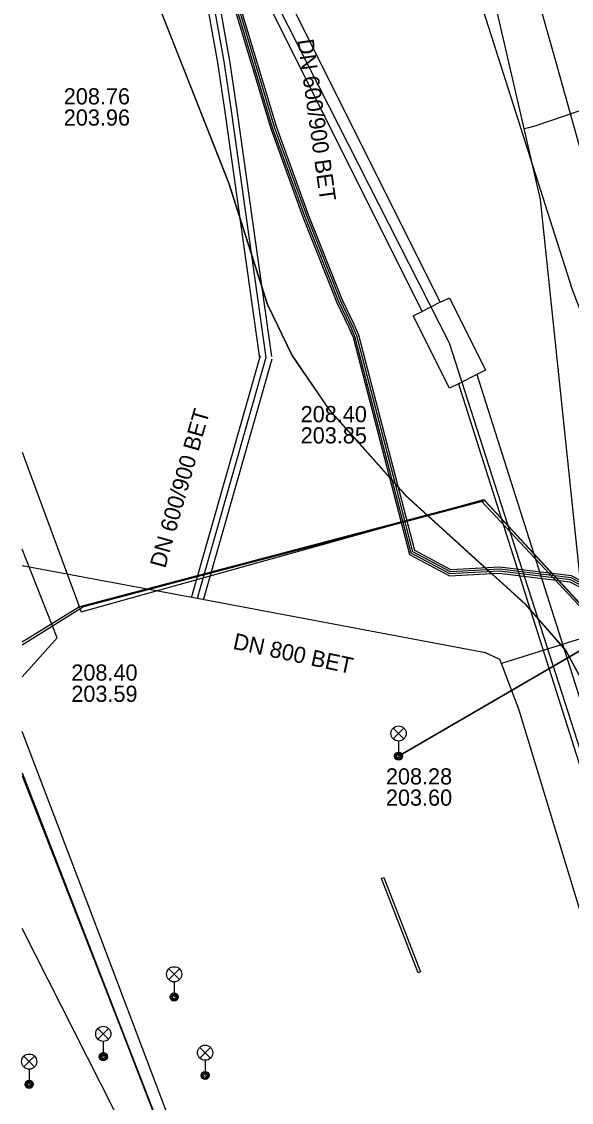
# Model space of a CAD drawing. Extents: x -595540 to -593988, y -1160850 to -1159202.
# Drawn here: x -595539.6 to -595512.4, y -1160240.3 to -1160186.8 of the extents above; entities that cross this region are included whole.
import ezdxf

# ---------------------------------------------------------------- set-up
doc = ezdxf.new("R2010")
doc.units = 0
for name, color, linetype in [('BKOM-ODVODNENI_objekt', 7, 'Continuous'), ('BKOM_kabel koordinační_optický', 7, 'Continuous'), ('BVK-JEDNOTNA_popisy', 7, 'Continuous'), ('BVK-JEDNOTNA_trasa sítě', 7, 'Continuous'), ('BVK-JEDNOTNA_trasa sítě obvodem', 7, 'Continuous'), ('BVK-VODOVOD_trasa sítě', 7, 'Continuous'), ('CETIN_kabel podzemní', 7, 'Continuous'), ('CETIN_kabelovod', 7, 'Continuous'), ('DPMB_trolejové vedení-nosné lano', 7, 'Continuous'), ('EON-SDEL_kabel', 7, 'Continuous'), ('EON-VN_kabel', 7, 'Continuous'), ('INNOGY-NTL_trasa sítě', 7, 'Continuous'), ('QUANTCOM_kabel', 7, 'Continuous'), ('TSB_kabel VO', 7, 'Continuous'), ('TSB_lampy VO', 7, 'Continuous')]:
    doc.layers.add(name, color=color, linetype=linetype)

msp = doc.modelspace()

# ---------------------------------------------------------------- linework, layer by layer
at = {"layer": 'BKOM-ODVODNENI_objekt'}
msp.add_lwpolyline([(-595520.01, -1160233.89), (-595521.83, -1160229.22), (-595521.71, -1160229.17), (-595519.89, -1160233.84)], close=True, dxfattribs=at)
at = {"layer": 'BKOM_kabel koordinační_optický'}
for points in [[(-595539.58, -1160219.244), (-595537.85, -1160217.31), (-595539.58, -1160212.925)], [(-595513.85, -1160288.56), (-595514.78, -1160289.19), (-595514.85, -1160286.98), (-595516.46, -1160285.31), (-595519.18, -1160278.38), (-595519.73, -1160274.57), (-595521.55, -1160271.88), (-595526.04, -1160260.69), (-595528.26, -1160254.82), (-595528.69, -1160251.43), (-595531.52, -1160243.2), (-595536.29, -1160230.6), (-595539.58, -1160221.945)]]:
    msp.add_lwpolyline(points, dxfattribs=at)
at = {"layer": 'BVK-JEDNOTNA_popisy'}
for p, q in [((-595537.522, -1160191.06), (-595537.522, -1160191.06)), ((-595525.817, -1160206.778), (-595525.817, -1160206.778)), ((-595537.15, -1160219.559), (-595537.15, -1160219.559)), ((-595521.606, -1160224.695), (-595521.606, -1160224.695))]:
    msp.add_line(p, q, dxfattribs=at)
at = {"layer": 'BVK-JEDNOTNA_trasa sítě'}
for p, q in [((-595529.245, -1160191.262), (-595527.537, -1160203.446)), ((-595527.537, -1160203.446), (-595530.93, -1160215.37)), ((-595530.93, -1160215.37), (-595539.58, -1160213.76))]:
    msp.add_line(p, q, dxfattribs=at)
for points in [[(-595539.58, -1160158.382), (-595538.785, -1160160.074), (-595537.726, -1160162.476), (-595536.956, -1160164.225), (-595536.25, -1160165.901), (-595535.634, -1160167.414), (-595534.973, -1160169.118), (-595534.34, -1160170.804), (-595533.479, -1160173.278), (-595532.719, -1160175.58), (-595531.904, -1160178.371), (-595530.872, -1160182.503), (-595530.202, -1160185.494), (-595529.609, -1160188.822), (-595529.245, -1160191.262)], [(-595502.779, -1160214.506), (-595504.78, -1160215.129), (-595506.59, -1160215.692), (-595512.412, -1160217.505), (-595515.893, -1160218.588)], [(-595515.893, -1160218.588), (-595515.969, -1160218.384), (-595516.679, -1160218.051), (-595530.93, -1160215.37)], [(-595501.932, -1160264.015), (-595515.017, -1160220.901), (-595515.893, -1160218.588)]]:
    msp.add_lwpolyline(points, dxfattribs=at)
at = {"layer": 'BVK-JEDNOTNA_trasa sítě obvodem'}
for p, q in [((-595527.834, -1160203.488), (-595529.542, -1160191.304)), ((-595527.24, -1160203.404), (-595528.948, -1160191.22)), ((-595527.826, -1160203.364), (-595531.219, -1160215.288)), ((-595527.248, -1160203.528), (-595530.641, -1160215.452))]:
    msp.add_line(p, q, dxfattribs=at)
for points in [[(-595528.948, -1160191.218), (-595529.313, -1160188.774), (-595529.907, -1160185.435), (-595530.58, -1160182.434), (-595531.614, -1160178.292), (-595532.432, -1160175.491), (-595533.195, -1160173.181), (-595534.057, -1160170.702), (-595534.693, -1160169.011), (-595535.356, -1160167.304), (-595535.973, -1160165.786), (-595536.681, -1160164.106), (-595537.451, -1160162.354), (-595538.512, -1160159.95), (-595539.58, -1160157.676)], [(-595529.542, -1160191.306), (-595529.905, -1160188.871), (-595530.496, -1160185.553), (-595531.164, -1160182.572), (-595532.193, -1160178.449), (-595533.005, -1160175.669), (-595533.763, -1160173.374), (-595534.622, -1160170.906), (-595535.254, -1160169.225), (-595535.913, -1160167.525), (-595536.527, -1160166.016), (-595537.232, -1160164.343), (-595538, -1160162.596), (-595539.058, -1160160.198), (-595539.58, -1160159.088)]]:
    msp.add_lwpolyline(points, dxfattribs=at)
at = {"layer": 'BVK-VODOVOD_trasa sítě'}
for points in [[(-595511.7, -1160217.366), (-595513.961, -1160195.642), (-595514.772, -1160192.124), (-595516.052, -1160186.573), (-595516.602, -1160184.188), (-595518.91, -1160174.175), (-595519.059, -1160173.529), (-595521.452, -1160170.03), (-595521.642, -1160169.757), (-595529.075, -1160158.883), (-595537.262, -1160146.913), (-595539.58, -1160143.525)], [(-595514.772, -1160192.124), (-595514.545, -1160192.072), (-595514.236, -1160192.001), (-595508.525, -1160190.053)]]:
    msp.add_lwpolyline(points, dxfattribs=at)
at = {"layer": 'CETIN_kabel podzemní'}
msp.add_lwpolyline([(-595502.07, -1160293.44), (-595490.46, -1160289.89), (-595518.47, -1160202.74), (-595539.4, -1160161.52), (-595539.58, -1160161.248)], dxfattribs=at)
at = {"layer": 'CETIN_kabelovod'}
for points in [[(-595537.6, -1160163.33), (-595518.92, -1160200.72)], [(-595538.44, -1160163.88), (-595519.81, -1160201.17)], [(-595518.92, -1160200.72), (-595519.81, -1160201.17)], [(-595518.92, -1160200.72), (-595518.47, -1160200.5), (-595516.68, -1160204.08), (-595517.12, -1160204.3)], [(-595518.02, -1160204.75), (-595518.46, -1160204.97), (-595520.26, -1160201.4), (-595519.81, -1160201.17)], [(-595517.12, -1160204.3), (-595518.02, -1160204.75)], [(-595517.12, -1160204.3), (-595490.74, -1160287.35)], [(-595518.02, -1160204.75), (-595491.7, -1160287.66)]]:
    msp.add_lwpolyline(points, dxfattribs=at)
at = {"layer": 'DPMB_trolejové vedení-nosné lano'}
msp.add_lwpolyline([(-595529.889, -1160250.835), (-595539.58, -1160231.693)], dxfattribs=at)
at = {"layer": 'EON-SDEL_kabel'}
for points in [[(-595539.58, -1160171.985), (-595537.716, -1160175.427), (-595534.786, -1160180.567), (-595532.666, -1160186.487), (-595529.366, -1160194.837), (-595527.456, -1160200.837), (-595526.236, -1160203.357), (-595524.406, -1160206.047), (-595521.43, -1160209.384), (-595521.139, -1160209.711), (-595520.616, -1160210.297), (-595516.6, -1160213.952), (-595516.392, -1160214.141), (-595514.716, -1160215.667), (-595512.716, -1160217.947), (-595510.466, -1160222.127), (-595508.176, -1160227.937), (-595507.99, -1160228.201)], [(-595529.119, -1160186.065), (-595527.3, -1160192.123), (-595525.687, -1160196.551), (-595524.023, -1160200.74), (-595523.452, -1160201.943), (-595523.229, -1160202.446), (-595521.43, -1160209.384), (-595520.442, -1160213.195), (-595518.465, -1160214.253), (-595516.392, -1160214.141), (-595516.007, -1160214.121), (-595512.52, -1160214.544), (-595507.042, -1160217.402), (-595505.473, -1160218.455), (-595504.631, -1160219.689), (-595504.625, -1160219.707), (-595503.142, -1160224.197), (-595501.133, -1160231.693), (-595499.333, -1160238.134), (-595497.192, -1160245.755)], [(-595497, -1160245.7), (-595499.14, -1160238.08), (-595500.94, -1160231.64), (-595502.95, -1160224.14), (-595504.45, -1160219.6), (-595504.491, -1160219.54), (-595505.33, -1160218.31), (-595506.94, -1160217.23), (-595512.46, -1160214.35), (-595516, -1160213.92), (-595516.6, -1160213.952), (-595518.42, -1160214.05), (-595520.27, -1160213.06), (-595521.139, -1160209.711), (-595523.04, -1160202.38), (-595523.271, -1160201.859), (-595523.84, -1160200.66), (-595525.5, -1160196.48), (-595527.11, -1160192.06), (-595528.93, -1160186)]]:
    msp.add_lwpolyline(points, dxfattribs=at)
at = {"layer": 'EON-VN_kabel'}
for points in [[(-595497.096, -1160245.727), (-595499.236, -1160238.107), (-595501.036, -1160231.666), (-595503.046, -1160224.169), (-595504.541, -1160219.645), (-595505.402, -1160218.382), (-595506.991, -1160217.316), (-595512.49, -1160214.447), (-595516.003, -1160214.02), (-595518.443, -1160214.151), (-595520.356, -1160213.127), (-595523.135, -1160202.413), (-595523.361, -1160201.902), (-595523.932, -1160200.7), (-595525.593, -1160196.516), (-595527.205, -1160192.092), (-595529.025, -1160186.032)], [(-595496.904, -1160245.673), (-595499.044, -1160238.053), (-595500.843, -1160231.614), (-595502.854, -1160224.111), (-595504.359, -1160219.555), (-595505.258, -1160218.238), (-595506.889, -1160217.144), (-595512.43, -1160214.253), (-595515.997, -1160213.82), (-595518.398, -1160213.949), (-595520.184, -1160212.993), (-595522.945, -1160202.347), (-595523.18, -1160201.817), (-595523.748, -1160200.62), (-595525.407, -1160196.444), (-595527.015, -1160192.028), (-595528.835, -1160185.968)]]:
    msp.add_lwpolyline(points, dxfattribs=at)
at = {"layer": 'INNOGY-NTL_trasa sítě'}
msp.add_lwpolyline([(-595506.82, -1160211.71), (-595507.03, -1160210.99), (-595508.06, -1160207.27), (-595509.9, -1160200.76), (-595511.13, -1160196.03), (-595512.1, -1160192.75), (-595513.19, -1160188.87), (-595514.44, -1160184.41), (-595514.56, -1160184.02), (-595514.76, -1160183.23), (-595515.33, -1160181.38), (-595516.49, -1160177.7), (-595519.3, -1160169.86), (-595519.39, -1160169.63), (-595519.63, -1160168.99), (-595519.78, -1160168.59), (-595519.92, -1160168.21), (-595519.58, -1160166.8), (-595525.76, -1160157.36)], dxfattribs=at)
at = {"layer": 'QUANTCOM_kabel'}
msp.add_lwpolyline([(-595507.99, -1160228.2), (-595508.17, -1160227.93), (-595510.46, -1160222.12), (-595512.71, -1160217.94), (-595514.71, -1160215.66), (-595520.61, -1160210.29), (-595524.4, -1160206.04), (-595526.23, -1160203.35), (-595527.45, -1160200.83), (-595529.36, -1160194.83), (-595532.66, -1160186.48), (-595534.78, -1160180.56), (-595537.71, -1160175.42), (-595539.58, -1160171.967)], dxfattribs=at)
at = {"layer": 'TSB_kabel VO'}
for points in [[(-595497.74, -1160230.67), (-595502.35, -1160228.99), (-595504.75, -1160218.47), (-595504.46, -1160214.78), (-595505.94, -1160214.71), (-595508.22, -1160206.5), (-595511.02, -1160203.66), (-595512.39, -1160200.1), (-595520.06, -1160176), (-595523.89, -1160167.79), (-595529.64, -1160159.03), (-595539.58, -1160144.314)], [(-595539.58, -1160208.135), (-595536.67, -1160216.03), (-595516.77, -1160210.48), (-595510.61, -1160217.142)], [(-595497.65, -1160230.7), (-595502.48, -1160228.88), (-595503.61, -1160224.76), (-595516.71, -1160210.54), (-595536.55, -1160215.78), (-595539.58, -1160217.688)], [(-595497.62, -1160230.7), (-595502.48, -1160229.07), (-595503.42, -1160224.95), (-595516.9, -1160210.54), (-595536.74, -1160215.78), (-595539.58, -1160217.533)], [(-595497.65, -1160230.7), (-595502.48, -1160229.07), (-595503.42, -1160224.95), (-595516.71, -1160210.54), (-595536.74, -1160215.78), (-595539.58, -1160217.533)], [(-595510.61, -1160217.142), (-595520.98, -1160223.17), (-595510.61, -1160217.142)], [(-595539.58, -1160223.991), (-595530.88, -1160246.43), (-595518.58, -1160278.48), (-595512.78, -1160294.77), (-595534.3, -1160302.07), (-595536.55, -1160296.26), (-595538.703, -1160293.66)], [(-595539.58, -1160224.012), (-595531.12, -1160245.92), (-595518.58, -1160278.3), (-595512.59, -1160294.95), (-595534.12, -1160302.07), (-595532.25, -1160308.24), (-595531.83, -1160309.236)], [(-595539.58, -1160224.14), (-595530.94, -1160246.29), (-595520.244, -1160274.255)]]:
    msp.add_lwpolyline(points, dxfattribs=at)
at = {"layer": 'TSB_lampy VO'}
for p, q in [((-595521.245, -1160222.31), (-595520.715, -1160221.78)), ((-595521.245, -1160221.78), (-595520.715, -1160222.31)), ((-595521.245, -1160222.31), (-595520.715, -1160221.78)), ((-595521.245, -1160221.78), (-595520.715, -1160222.31)), ((-595520.98, -1160222.42), (-595520.98, -1160223.17)), ((-595520.98, -1160222.42), (-595520.98, -1160223.17)), ((-595532.335, -1160234.22), (-595531.805, -1160233.69)), ((-595532.335, -1160233.69), (-595531.805, -1160234.22)), ((-595532.335, -1160234.22), (-595531.805, -1160233.69)), ((-595532.335, -1160233.69), (-595531.805, -1160234.22)), ((-595532.07, -1160234.33), (-595532.07, -1160235.08)), ((-595532.07, -1160234.33), (-595532.07, -1160235.08)), ((-595535.835, -1160237.17), (-595535.305, -1160236.64)), ((-595535.835, -1160236.64), (-595535.305, -1160237.17)), ((-595535.835, -1160237.17), (-595535.305, -1160236.64)), ((-595535.835, -1160236.64), (-595535.305, -1160237.17)), ((-595535.57, -1160237.28), (-595535.57, -1160238.03)), ((-595535.57, -1160237.28), (-595535.57, -1160238.03)), ((-595530.805, -1160238.1), (-595530.275, -1160237.57)), ((-595530.805, -1160237.57), (-595530.275, -1160238.1)), ((-595530.805, -1160238.1), (-595530.275, -1160237.57)), ((-595530.805, -1160237.57), (-595530.275, -1160238.1)), ((-595539.495, -1160238.54), (-595538.965, -1160238.01)), ((-595539.495, -1160238.01), (-595538.965, -1160238.54)), ((-595539.495, -1160238.54), (-595538.965, -1160238.01)), ((-595539.495, -1160238.01), (-595538.965, -1160238.54)), ((-595530.54, -1160238.21), (-595530.54, -1160238.96)), ((-595530.54, -1160238.21), (-595530.54, -1160238.96)), ((-595539.23, -1160238.65), (-595539.23, -1160239.4)), ((-595539.23, -1160238.65), (-595539.23, -1160239.4))]:
    msp.add_line(p, q, dxfattribs=at)
for centre, radius in [((-595520.98, -1160222.045), 0.375), ((-595520.98, -1160222.045), 0.375), ((-595520.98, -1160223.17), 0.2), ((-595520.98, -1160223.17), 0.2), ((-595520.98, -1160223.17), 0.145), ((-595520.98, -1160223.17), 0.145), ((-595520.98, -1160223.17), 0.0876), ((-595520.98, -1160223.17), 0.0876), ((-595532.07, -1160233.955), 0.375), ((-595532.07, -1160233.955), 0.375), ((-595532.07, -1160235.08), 0.2), ((-595532.07, -1160235.08), 0.2), ((-595532.07, -1160235.08), 0.145), ((-595532.07, -1160235.08), 0.145), ((-595532.07, -1160235.08), 0.0876), ((-595532.07, -1160235.08), 0.0876), ((-595535.57, -1160236.905), 0.375), ((-595535.57, -1160236.905), 0.375), ((-595530.54, -1160237.835), 0.375), ((-595530.54, -1160237.835), 0.375), ((-595539.23, -1160238.275), 0.375), ((-595539.23, -1160238.275), 0.375), ((-595535.57, -1160238.03), 0.2), ((-595535.57, -1160238.03), 0.2), ((-595535.57, -1160238.03), 0.145), ((-595535.57, -1160238.03), 0.145), ((-595535.57, -1160238.03), 0.0876), ((-595535.57, -1160238.03), 0.0876), ((-595530.54, -1160238.96), 0.2), ((-595530.54, -1160238.96), 0.2), ((-595539.23, -1160239.4), 0.2), ((-595539.23, -1160239.4), 0.2), ((-595539.23, -1160239.4), 0.145), ((-595539.23, -1160239.4), 0.145), ((-595539.23, -1160239.4), 0.0876), ((-595539.23, -1160239.4), 0.0876), ((-595530.54, -1160238.96), 0.145), ((-595530.54, -1160238.96), 0.145), ((-595530.54, -1160238.96), 0.0876), ((-595530.54, -1160238.96), 0.0876)]:
    msp.add_circle(centre, radius, dxfattribs=at)

# ---------------------------------------------------------------- texts
at = {"layer": 'BVK-JEDNOTNA_popisy'}
for s, rotation, p in [('DN 600/900 BET', 277.9796, (-595525.979, -1160187.754)), ('DN 600/900 BET', 74.1407, (-595532.512, -1160213.913)), ('DN 800 BET', 347.9378, (-595529.203, -1160217.853))]:
    msp.add_text(s, height=0.8, rotation=rotation, dxfattribs=at).set_placement(p)
for s, p in [('208.76', (-595537.522, -1160190.935)), ('203.96', (-595537.522, -1160191.985)), ('208.40', (-595525.817, -1160206.653)), ('203.85', (-595525.817, -1160207.703)), ('208.40', (-595537.15, -1160219.434)), ('203.59', (-595537.15, -1160220.484)), ('208.28', (-595521.606, -1160224.57)), ('203.60', (-595521.606, -1160225.62))]:
    msp.add_text(s, height=0.8, dxfattribs=at).set_placement(p)

doc.saveas('drawing.dxf')
